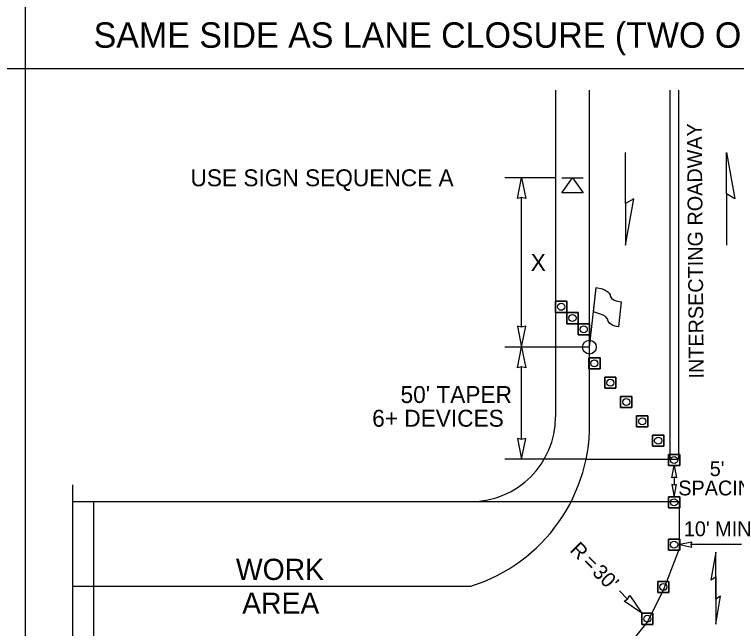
# Model space of a CAD drawing. Extents: x 99999.1 to 100095.7, y 99995 to 100010.7.
# Drawn here: x 100065.2 to 100068.61, y 100003.336 to 100006.238 of the extents above; entities that cross this region are included whole.
import ezdxf

# ---------------------------------------------------------------- set-up
doc = ezdxf.new("R2010")
doc.units = 0
for name, color, linetype in [('RD_ED_ShoulderPavedEdge', 7, 'Continuous'), ('RD_MK_LineDblYellowCenter', 7, 'Continuous'), ('RD_MK_LineEdgeWhite', 7, 'Continuous'), ('RD_MK_LineStop', 7, 'Continuous'), ('SH_DE_DetailBody1Text', 7, 'Continuous'), ('SH_DE_DetailHeading2Text', 7, 'Continuous'), ('TR_WZ_FlaggingStation', 7, 'Continuous'), ('TR_WZ_PortableSignMountBlk-Org', 7, 'Continuous'), ('TR_WZ_TrafficCone', 7, 'Continuous'), ('TR_WZ_WorkAreaLabel', 7, 'Continuous'), ('TR_WZ_WorkZoneDetails', 7, 'Continuous'), ('TR_WZ_WorkZoneTextCurrent', 7, 'Continuous')]:
    doc.layers.add(name, color=color, linetype=linetype)

msp = doc.modelspace()

# ---------------------------------------------------------------- linework, layer by layer
at = {"layer": 'RD_ED_ShoulderPavedEdge'}
msp.add_line((100065.475, 100003.9359), (100067.355, 100003.9359), dxfattribs=at)
msp.add_lwpolyline([(100067.755, 100005.8804), (100067.755, 100004.3359)], dxfattribs=at)
msp.add_arc((100067.355, 100004.3359), 0.4, 270, 0, dxfattribs=at)
at = {"layer": 'RD_MK_LineDblYellowCenter'}
for p, q in [((100068.295, 100005.8804), (100068.295, 100004.1359)), ((100068.335, 100005.8804), (100068.335, 100004.1359))]:
    msp.add_line(p, q, dxfattribs=at)
at = {"layer": 'RD_MK_LineEdgeWhite'}
for p, q in [((100067.915, 100004.3359), (100067.915, 100005.8804)), ((100065.475, 100003.5359), (100067.355, 100003.5359))]:
    msp.add_line(p, q, dxfattribs=at)
msp.add_arc((100067.1158, 100004.2993), 0.8, 287.3948, 2.6212, dxfattribs=at)
at = {"layer": 'RD_MK_LineStop'}
msp.add_line((100067.899, 100004.1359), (100068.335, 100004.1359), dxfattribs=at)
at = {"layer": 'TR_WZ_FlaggingStation'}
for p, q in [((100067.915, 100004.6659), (100067.9471, 100004.9468)), ((100067.934, 100004.8328), (100067.9471, 100004.9471)), ((100068.065, 100004.8793), (100068.0517, 100004.7621)), ((100067.934, 100004.8328), (100067.934, 100004.8328))]:
    msp.add_line(p, q, dxfattribs=at)
for points in [[(100067.9471, 100004.9471), (100067.9528, 100004.9459), (100067.9707, 100004.9424), (100067.9845, 100004.9383), (100067.9942, 100004.9322), (100068.0027, 100004.9275), (100068.0084, 100004.9206), (100068.0126, 100004.9128), (100068.0131, 100004.9066), (100068.0185, 100004.8974), (100068.0293, 100004.8899), (100068.0417, 100004.8847), (100068.065, 100004.8793)], [(100068.0517, 100004.7621), (100068.0436, 100004.7636), (100068.0259, 100004.7682), (100068.0103, 100004.7787), (100068.0037, 100004.7893), (100067.9998, 100004.7996), (100067.9907, 100004.8105), (100067.9798, 100004.8167), (100067.9624, 100004.8238), (100067.934, 100004.8328)]]:
    msp.add_lwpolyline(points, dxfattribs=at)
msp.add_circle((100067.915, 100004.6659), 0.0325, dxfattribs=at)
at = {"layer": 'TR_WZ_PortableSignMountBlk-Org'}
msp.add_line((100067.785, 100005.4659), (100067.885, 100005.4659), dxfattribs=at)
msp.add_lwpolyline([(100067.8349, 100005.4659), (100067.885, 100005.3941), (100067.785, 100005.3941)], close=True, dxfattribs=at)
at = {"layer": 'TR_WZ_TrafficCone'}
for points in [[(100067.8083, 100004.8833), (100067.8083, 100004.8299), (100067.755, 100004.8299), (100067.755, 100004.8833), (100067.8083, 100004.8833)], [(100067.755, 100004.8833), (100067.755, 100004.8299), (100067.8083, 100004.8299), (100067.8083, 100004.8833), (100067.755, 100004.8833)], [(100067.8617, 100004.8299), (100067.8617, 100004.7766), (100067.8083, 100004.7766), (100067.8083, 100004.8299), (100067.8617, 100004.8299)], [(100067.8083, 100004.8299), (100067.8083, 100004.7766), (100067.8617, 100004.7766), (100067.8617, 100004.8299), (100067.8083, 100004.8299)], [(100067.915, 100004.7766), (100067.915, 100004.7233), (100067.8617, 100004.7233), (100067.8617, 100004.7766), (100067.915, 100004.7766)], [(100067.8617, 100004.7766), (100067.8617, 100004.7233), (100067.915, 100004.7233), (100067.915, 100004.7766), (100067.8617, 100004.7766)], [(100067.9117, 100004.6159), (100067.965, 100004.6159), (100067.965, 100004.5626), (100067.9117, 100004.5626), (100067.9117, 100004.6159)], [(100067.9117, 100004.5626), (100067.965, 100004.5626), (100067.965, 100004.6159), (100067.9117, 100004.6159), (100067.9117, 100004.5626)], [(100067.987, 100004.5246), (100068.0404, 100004.5246), (100068.0404, 100004.4712), (100067.987, 100004.4712), (100067.987, 100004.5246)], [(100067.987, 100004.4712), (100068.0404, 100004.4712), (100068.0404, 100004.5246), (100067.987, 100004.5246), (100067.987, 100004.4712)], [(100068.0624, 100004.4332), (100068.1157, 100004.4332), (100068.1157, 100004.3799), (100068.0624, 100004.3799), (100068.0624, 100004.4332)], [(100068.0624, 100004.3799), (100068.1157, 100004.3799), (100068.1157, 100004.4332), (100068.0624, 100004.4332), (100068.0624, 100004.3799)], [(100068.1377, 100004.3419), (100068.191, 100004.3419), (100068.191, 100004.2886), (100068.1377, 100004.2886), (100068.1377, 100004.3419)], [(100068.1377, 100004.2886), (100068.191, 100004.2886), (100068.191, 100004.3419), (100068.1377, 100004.3419), (100068.1377, 100004.2886)], [(100068.213, 100004.2506), (100068.2664, 100004.2506), (100068.2664, 100004.1972), (100068.213, 100004.1972), (100068.213, 100004.2506)], [(100068.213, 100004.1972), (100068.2664, 100004.1972), (100068.2664, 100004.2506), (100068.213, 100004.2506), (100068.213, 100004.1972)], [(100068.2884, 100004.1592), (100068.3417, 100004.1592), (100068.3417, 100004.1059), (100068.2884, 100004.1059), (100068.2884, 100004.1592)], [(100068.2884, 100004.1059), (100068.3417, 100004.1059), (100068.3417, 100004.1592), (100068.2884, 100004.1592), (100068.2884, 100004.1059)], [(100068.2884, 100003.9592), (100068.3417, 100003.9592), (100068.3417, 100003.9059), (100068.2884, 100003.9059), (100068.2884, 100003.9592)], [(100068.2884, 100003.9059), (100068.3417, 100003.9059), (100068.3417, 100003.9592), (100068.2884, 100003.9592), (100068.2884, 100003.9059)], [(100068.2884, 100003.7592), (100068.3417, 100003.7592), (100068.3417, 100003.7059), (100068.2884, 100003.7059), (100068.2884, 100003.7592)], [(100068.2884, 100003.7059), (100068.3417, 100003.7059), (100068.3417, 100003.7592), (100068.2884, 100003.7592), (100068.2884, 100003.7059)], [(100068.2373, 100003.5592), (100068.2907, 100003.5592), (100068.2907, 100003.5059), (100068.2373, 100003.5059), (100068.2373, 100003.5592)], [(100068.2373, 100003.5059), (100068.2907, 100003.5059), (100068.2907, 100003.5592), (100068.2373, 100003.5592), (100068.2373, 100003.5059)], [(100068.1617, 100003.4093), (100068.215, 100003.4093), (100068.215, 100003.3559), (100068.1617, 100003.3559), (100068.1617, 100003.4093)], [(100068.1617, 100003.3559), (100068.215, 100003.3559), (100068.215, 100003.4093), (100068.1617, 100003.4093), (100068.1617, 100003.3559)]]:
    msp.add_lwpolyline(points, dxfattribs=at)
for centre in [(100067.7817, 100004.8566), (100067.835, 100004.8033), (100067.8883, 100004.7499), (100067.9384, 100004.5892), (100068.0137, 100004.4979), (100068.089, 100004.4066), (100068.1644, 100004.3152), (100068.2397, 100004.2239), (100068.315, 100004.1326), (100068.315, 100003.9326), (100068.315, 100003.7326), (100068.264, 100003.5326), (100068.1883, 100003.3826)]:
    msp.add_circle(centre, 0.0167, dxfattribs=at)
at = {"layer": 'TR_WZ_WorkZoneDetails'}
for p, q in [((100065.25, 100010.275), (100065.25, 100001.6859)), ((100065.25, 100005.9804), (100060, 100005.9804)), ((100070.5, 100005.9804), (100065.25, 100005.9804)), ((100068.0855, 100005.3448), (100068.0855, 100005.5859)), ((100067.755, 100005.4659), (100067.515, 100005.4659)), ((100068.5627, 100005.3894), (100068.5627, 100005.1483)), ((100067.595, 100004.7596), (100067.595, 100005.3722)), ((100067.915, 100004.6659), (100067.515, 100004.6659)), ((100067.595, 100004.2296), (100067.595, 100004.5722)), ((100067.899, 100004.1359), (100067.515, 100004.1359)), ((100068.3151, 100004.0514), (100068.3151, 100004.0137)), ((100068.6338, 100003.7326), (100068.3962, 100003.7326)), ((100068.5115, 100003.4752), (100068.5115, 100003.6199)), ((100068.5115, 100003.5799), (100068.5115, 100003.4352)), ((100068.0954, 100003.4755), (100068.057, 100003.514))]:
    msp.add_line(p, q, dxfattribs=at)
for points in [[(100068.5627, 100005.5859), (100068.6013, 100005.3671), (100068.5627, 100005.3894)], [(100067.595, 100005.4659), (100067.6143, 100005.3676), (100067.595, 100005.3722), (100067.5757, 100005.3676)], [(100068.0855, 100005.1483), (100068.124, 100005.3671), (100068.0855, 100005.3448)], [(100067.595, 100004.6659), (100067.6143, 100004.7642), (100067.595, 100004.7596), (100067.5757, 100004.7642)], [(100067.595, 100004.6659), (100067.6143, 100004.5676), (100067.595, 100004.5722), (100067.5757, 100004.5676)], [(100067.595, 100004.1359), (100067.6143, 100004.2342), (100067.595, 100004.2296), (100067.5757, 100004.2342)], [(100068.315, 100004.1059), (100068.3263, 100004.0487), (100068.315, 100004.0514), (100068.3038, 100004.0487)], [(100068.3151, 100003.9592), (100068.3263, 100004.0164), (100068.3151, 100004.0137), (100068.3039, 100004.0164)], [(100068.3383, 100003.9359), (100068.3383, 100003.7126), (100068.264, 100003.5159), (100068.1883, 100003.3659), (100068.1883, 100003.3659), (100068.1883, 100003.3659), (100068.0714, 100003.2236), (100068.0714, 100003.2236), (100068.0714, 100003.2236), (100067.8797, 100003.0868), (100067.699, 100003.0359), (100066.499, 100003.0359), (100065.699, 100003.0359), (100065.575, 100003.0359), (100065.575, 100003.9359)], [(100068.3417, 100003.7326), (100068.3989, 100003.7214), (100068.3962, 100003.7326), (100068.3989, 100003.7438)], [(100068.5115, 100003.6978), (100068.4883, 100003.5665), (100068.5115, 100003.5799)], [(100068.1617, 100003.4093), (100068.0786, 100003.4652), (100068.0954, 100003.4756), (100068.1058, 100003.4924)], [(100068.5115, 100003.3573), (100068.5346, 100003.4886), (100068.5115, 100003.4752)]]:
    msp.add_lwpolyline(points, close=True, dxfattribs=at)
msp.add_lwpolyline([(100065.475, 100002.0959), (100065.475, 100002.9785), (100065.395, 100002.9785), (100065.555, 100003.1333), (100065.475, 100003.1333), (100065.475, 100004.0159)], dxfattribs=at)

# ---------------------------------------------------------------- texts
at = {"layer": 'SH_DE_DetailBody1Text'}
msp.add_text('INTERSECTING ROADWAY', height=0.07, rotation=90.4626, dxfattribs=at).set_placement((100068.455, 100004.5177))
at = {"layer": 'SH_DE_DetailHeading2Text'}
msp.add_text('SAME SIDE AS LANE CLOSURE (TWO OPEN LANES)', height=0.12, rotation=360, dxfattribs=at).set_placement((100065.5738, 100006.0804))
at = {"layer": 'TR_WZ_WorkAreaLabel'}
for s, p in [('WORK', (100066.2458, 100003.5659)), ('AREA', (100066.2754, 100003.4059))]:
    msp.add_text(s, height=0.1, dxfattribs=at).set_placement(p)
at = {"layer": 'TR_WZ_WorkZoneTextCurrent'}
for s, height, p in [('USE SIGN SEQUENCE A', 0.08, (100066.0313, 100005.4259)), ('X', 0.08, (100067.6379, 100005.0259)), ("50' TAPER", 0.08, (100067.0232, 100004.4019)), ('6+ DEVICES', 0.08, (100066.8892, 100004.2899)), ("5'", 0.07, (100068.483, 100004.0564)), ('SPACING', 0.07, (100068.3346, 100003.9654)), ("10' MIN", 0.07, (100068.3608, 100003.7726))]:
    msp.add_text(s, height=height, dxfattribs=at).set_placement(p)
for s, p in [('R', (100067.8182, 100003.7032)), ('=', (100067.8774, 100003.644)), ("30'", (100067.9242, 100003.5972))]:
    msp.add_text(s, height=0.07, rotation=315, dxfattribs=at).set_placement(p)

doc.saveas('drawing.dxf')
